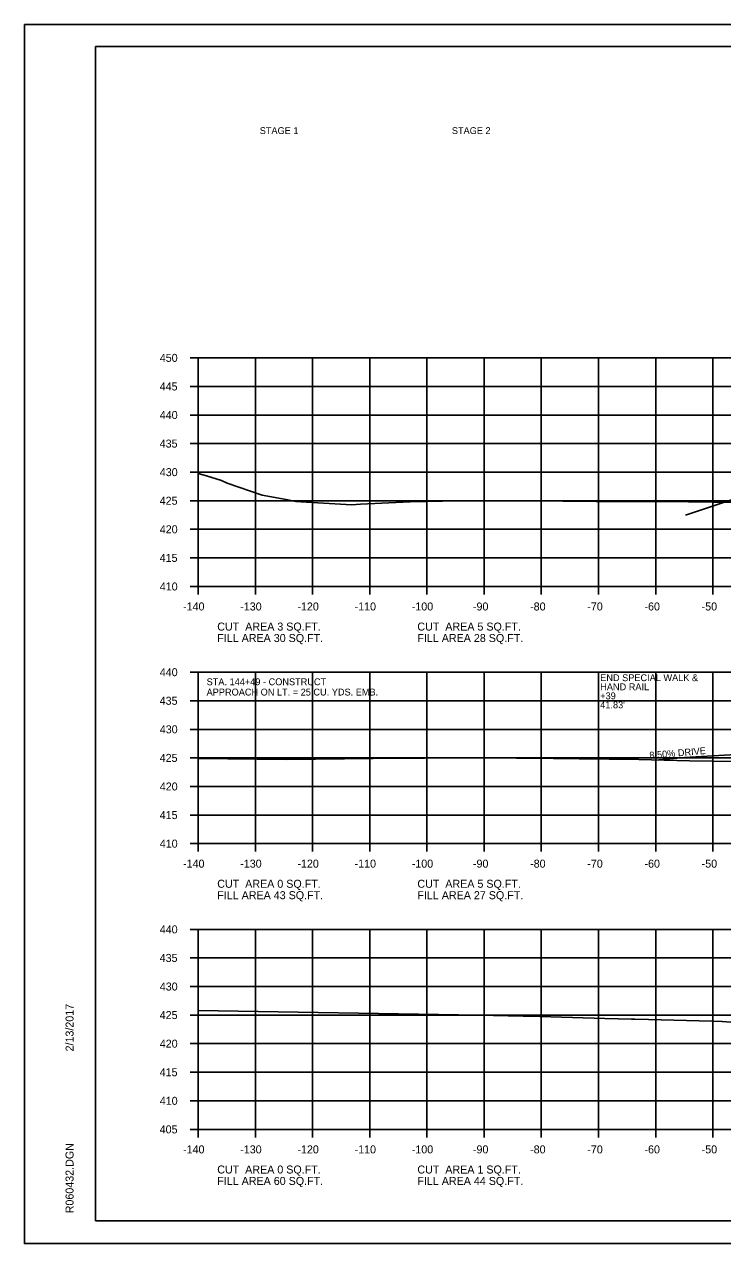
# Model space of a CAD drawing. Extents: x 1538688 to 1540766, y 656250 to 671912.
# Drawn here: x 1538687.8 to 1538809.9, y 663164.7 to 663378.1 of the extents above; entities that cross this region are included whole.
import ezdxf

# ---------------------------------------------------------------- set-up
doc = ezdxf.new("R2010")
doc.units = 0
for name, color, linetype in [('16', 7, 'Continuous'), ('18', 7, 'Continuous'), ('22', 7, 'Continuous'), ('26', 7, 'Continuous'), ('7', 7, 'Continuous'), ('Borings', 7, 'Continuous'), ('Default', 7, 'Continuous'), ('Horizontal Alignment', 7, 'Continuous'), ('RipRap', 7, 'Continuous')]:
    doc.layers.add(name, color=color, linetype=linetype)

msp = doc.modelspace()

# ---------------------------------------------------------------- linework, layer by layer
at = {"layer": '16'}
for p, q in [((1538798.14, 663249.33), (1538803.21, 663249.76)), ((1538803.21, 663249.76), (1538813.2, 663250.36))]:
    msp.add_line(p, q, dxfattribs=at)
at = {"layer": '18'}
for points in [[(1538718.18, 663299.49), (1538719.63, 663299.03), (1538722.26, 663298.22), (1538723.24, 663297.8), (1538729.37, 663295.65), (1538733.58, 663294.89), (1538735.27, 663294.58), (1538736.12, 663294.5), (1538745.06, 663294), (1538746.56, 663294.1), (1538755.22, 663294.53), (1538760.88, 663294.62), (1538767.87, 663294.66), (1538770.41, 663294.68), (1538781.93, 663294.6), (1538787.76, 663294.56), (1538799.62, 663294.54), (1538816.79, 663294.35)], [(1538718.18, 663249.57), (1538733.69, 663249.4), (1538753.85, 663249.63), (1538757.76, 663249.64), (1538761.4, 663249.69), (1538761.85, 663249.72), (1538763.1, 663249.71), (1538767.33, 663249.69), (1538780.28, 663249.62), (1538784.81, 663249.53), (1538795.23, 663249.4), (1538804.12, 663249.2), (1538816.39, 663249.02)], [(1538718.18, 663205.48), (1538767.19, 663204.69), (1538775.02, 663204.52), (1538775.4, 663204.52), (1538776.03, 663204.49), (1538789.31, 663204.11), (1538793.98, 663203.98), (1538794.55, 663203.96), (1538796.93, 663203.9), (1538808.02, 663203.62), (1538809.78, 663203.55), (1538818.94, 663202.89)]]:
    msp.add_lwpolyline(points, dxfattribs=at)
at = {"layer": '22'}
for p, q in [((1538718.18, 663319.7), (1538998.18, 663319.7)), ((1538718.18, 663279.7), (1538718.18, 663319.7)), ((1538728.18, 663279.7), (1538728.18, 663319.7)), ((1538738.18, 663279.7), (1538738.18, 663319.7)), ((1538748.18, 663279.7), (1538748.18, 663319.7)), ((1538758.18, 663279.7), (1538758.18, 663319.7)), ((1538768.18, 663279.7), (1538768.18, 663319.7)), ((1538778.18, 663279.7), (1538778.18, 663319.7)), ((1538788.18, 663279.7), (1538788.18, 663319.7)), ((1538798.18, 663279.7), (1538798.18, 663319.7)), ((1538808.18, 663279.7), (1538808.18, 663319.7)), ((1538718.18, 663314.7), (1538998.18, 663314.7)), ((1538718.18, 663309.7), (1538998.18, 663309.7)), ((1538718.18, 663304.7), (1538998.18, 663304.7)), ((1538718.18, 663299.7), (1538998.18, 663299.7)), ((1538718.18, 663294.7), (1538998.18, 663294.7)), ((1538718.18, 663289.7), (1538998.18, 663289.7)), ((1538718.18, 663284.7), (1538998.18, 663284.7)), ((1538718.18, 663279.7), (1538998.18, 663279.7)), ((1538718.18, 663264.7), (1538998.18, 663264.7)), ((1538718.18, 663234.7), (1538718.18, 663264.7)), ((1538728.18, 663234.7), (1538728.18, 663264.7)), ((1538738.18, 663234.7), (1538738.18, 663264.7)), ((1538748.18, 663234.7), (1538748.18, 663264.7)), ((1538758.18, 663234.7), (1538758.18, 663264.7)), ((1538768.18, 663234.7), (1538768.18, 663264.7)), ((1538778.18, 663234.7), (1538778.18, 663264.7)), ((1538788.18, 663234.7), (1538788.18, 663264.7)), ((1538798.18, 663234.7), (1538798.18, 663264.7)), ((1538808.18, 663234.7), (1538808.18, 663264.7)), ((1538718.18, 663259.7), (1538998.18, 663259.7)), ((1538718.18, 663254.7), (1538998.18, 663254.7)), ((1538718.18, 663249.7), (1538998.18, 663249.7)), ((1538718.18, 663244.7), (1538998.18, 663244.7)), ((1538718.18, 663239.7), (1538998.18, 663239.7)), ((1538718.18, 663234.7), (1538998.18, 663234.7)), ((1538718.18, 663219.7), (1538998.18, 663219.7)), ((1538718.18, 663184.7), (1538718.18, 663219.7)), ((1538728.18, 663184.7), (1538728.18, 663219.7)), ((1538738.18, 663184.7), (1538738.18, 663219.7)), ((1538748.18, 663184.7), (1538748.18, 663219.7)), ((1538758.18, 663184.7), (1538758.18, 663219.7)), ((1538768.18, 663184.7), (1538768.18, 663219.7)), ((1538778.18, 663184.7), (1538778.18, 663219.7)), ((1538788.18, 663184.7), (1538788.18, 663219.7)), ((1538798.18, 663184.7), (1538798.18, 663219.7)), ((1538808.18, 663184.7), (1538808.18, 663219.7)), ((1538718.18, 663214.7), (1538998.18, 663214.7)), ((1538718.18, 663209.7), (1538998.18, 663209.7)), ((1538718.18, 663204.7), (1538998.18, 663204.7)), ((1538718.18, 663199.7), (1538998.18, 663199.7)), ((1538718.18, 663194.7), (1538998.18, 663194.7)), ((1538718.18, 663189.7), (1538998.18, 663189.7)), ((1538718.18, 663184.7), (1538998.18, 663184.7))]:
    msp.add_line(p, q, dxfattribs=at)
at = {"layer": '26'}
for p, q in [((1538687.78, 663378.05), (1539021.11, 663378.05)), ((1538687.78, 663164.72), (1539021.11, 663164.72))]:
    msp.add_line(p, q, dxfattribs=at)
msp.add_lwpolyline([(1538687.77, 663378.05), (1539021.11, 663378.05), (1539021.11, 663164.71), (1538687.77, 663164.71)], close=True, dxfattribs=at)
msp.add_lwpolyline([(1538816.67, 663296.6), (1538811.99, 663295.04), (1538803.4, 663292.18)], dxfattribs=at)
at = {"layer": 'Borings'}
for p, q in [((1538716.78, 663319.7), (1538718.18, 663319.7)), ((1538718.18, 663279.7), (1538718.18, 663319.7)), ((1538716.78, 663314.7), (1538718.18, 663314.7)), ((1538716.78, 663309.7), (1538718.18, 663309.7)), ((1538716.78, 663304.7), (1538718.18, 663304.7)), ((1538716.78, 663299.7), (1538718.18, 663299.7)), ((1538716.78, 663294.7), (1538718.18, 663294.7)), ((1538716.78, 663289.7), (1538718.18, 663289.7)), ((1538716.78, 663284.7), (1538718.18, 663284.7)), ((1538716.78, 663279.7), (1538718.18, 663279.7)), ((1538718.18, 663279.7), (1538998.18, 663279.7)), ((1538718.18, 663278.3), (1538718.18, 663279.7)), ((1538728.18, 663278.3), (1538728.18, 663279.7)), ((1538738.18, 663278.3), (1538738.18, 663279.7)), ((1538748.18, 663278.3), (1538748.18, 663279.7)), ((1538758.18, 663278.3), (1538758.18, 663279.7)), ((1538768.18, 663278.3), (1538768.18, 663279.7)), ((1538778.18, 663278.3), (1538778.18, 663279.7)), ((1538788.18, 663278.3), (1538788.18, 663279.7)), ((1538798.18, 663278.3), (1538798.18, 663279.7)), ((1538808.18, 663278.3), (1538808.18, 663279.7)), ((1538716.78, 663264.7), (1538718.18, 663264.7)), ((1538718.18, 663234.7), (1538718.18, 663264.7)), ((1538716.78, 663259.7), (1538718.18, 663259.7)), ((1538716.78, 663254.7), (1538718.18, 663254.7)), ((1538716.78, 663249.7), (1538718.18, 663249.7)), ((1538716.78, 663244.7), (1538718.18, 663244.7)), ((1538716.78, 663239.7), (1538718.18, 663239.7)), ((1538716.78, 663234.7), (1538718.18, 663234.7)), ((1538718.18, 663234.7), (1538998.18, 663234.7)), ((1538718.18, 663233.3), (1538718.18, 663234.7)), ((1538728.18, 663233.3), (1538728.18, 663234.7)), ((1538738.18, 663233.3), (1538738.18, 663234.7)), ((1538748.18, 663233.3), (1538748.18, 663234.7)), ((1538758.18, 663233.3), (1538758.18, 663234.7)), ((1538768.18, 663233.3), (1538768.18, 663234.7)), ((1538778.18, 663233.3), (1538778.18, 663234.7)), ((1538788.18, 663233.3), (1538788.18, 663234.7)), ((1538798.18, 663233.3), (1538798.18, 663234.7)), ((1538808.18, 663233.3), (1538808.18, 663234.7)), ((1538716.78, 663219.7), (1538718.18, 663219.7)), ((1538718.18, 663184.7), (1538718.18, 663219.7)), ((1538716.78, 663214.7), (1538718.18, 663214.7)), ((1538716.78, 663209.7), (1538718.18, 663209.7)), ((1538716.78, 663204.7), (1538718.18, 663204.7)), ((1538716.78, 663199.7), (1538718.18, 663199.7)), ((1538716.78, 663194.7), (1538718.18, 663194.7)), ((1538716.78, 663189.7), (1538718.18, 663189.7)), ((1538716.78, 663184.7), (1538718.18, 663184.7)), ((1538718.18, 663184.7), (1538998.18, 663184.7)), ((1538718.18, 663183.3), (1538718.18, 663184.7)), ((1538728.18, 663183.3), (1538728.18, 663184.7)), ((1538738.18, 663183.3), (1538738.18, 663184.7)), ((1538748.18, 663183.3), (1538748.18, 663184.7)), ((1538758.18, 663183.3), (1538758.18, 663184.7)), ((1538768.18, 663183.3), (1538768.18, 663184.7)), ((1538778.18, 663183.3), (1538778.18, 663184.7)), ((1538788.18, 663183.3), (1538788.18, 663184.7)), ((1538798.18, 663183.3), (1538798.18, 663184.7)), ((1538808.18, 663183.3), (1538808.18, 663184.7))]:
    msp.add_line(p, q, dxfattribs=at)
at = {"layer": 'RipRap'}
for p, q in [((1538700.18, 663374.16), (1539016.36, 663374.16)), ((1538700.18, 663168.7), (1538700.18, 663374.16)), ((1538700.18, 663168.7), (1538700.18, 663168.7)), ((1539016.36, 663168.7), (1538700.18, 663168.7))]:
    msp.add_line(p, q, dxfattribs=at)

# ---------------------------------------------------------------- texts
at = {"layer": '16'}
msp.add_text('8.50% DRIVE', height=1.2, rotation=4.8585, dxfattribs=at).set_placement((1538797.13, 663249.55))
at = {"layer": '7'}
for s, p in [('STA. 144+49 - CONSTRUCT', (1538719.64, 663262.42)), ('END SPECIAL WALK &', (1538788.48, 663263.13)), ('HAND RAIL', (1538788.48, 663261.54)), ('APPROACH ON LT. = 25 CU. YDS. EMB.', (1538719.64, 663260.62)), ('+39', (1538788.48, 663259.96)), ("41.83'", (1538788.48, 663258.38))]:
    msp.add_text(s, height=1.2, dxfattribs=at).set_placement(p)
at = {"layer": 'Default'}
for s, p in [('STAGE 1', (1538728.93, 663358.86)), ('STAGE 2', (1538762.53, 663358.86))]:
    msp.add_text(s, height=1.2, dxfattribs=at).set_placement(p)
at = {"layer": 'Horizontal Alignment'}
for s, p in [('450', (1538711.45, 663319)), ('445', (1538711.43, 663314)), ('440', (1538711.45, 663309)), ('435', (1538711.43, 663304)), ('430', (1538711.45, 663299)), ('425', (1538711.43, 663294)), ('420', (1538711.45, 663289)), ('415', (1538711.43, 663284)), ('410', (1538711.45, 663279)), ('-140', (1538715.52, 663275.5)), ('-130', (1538725.52, 663275.5)), ('-120', (1538735.52, 663275.5)), ('-110', (1538745.52, 663275.5)), ('-100', (1538755.52, 663275.5)), ('-90', (1538766.22, 663275.5)), ('-80', (1538776.22, 663275.5)), ('-70', (1538786.22, 663275.5)), ('-60', (1538796.22, 663275.5)), ('-50', (1538806.22, 663275.5)), ('CUT  AREA 3 SQ.FT.', (1538721.5, 663271.98)), ('CUT  AREA 5 SQ.FT.', (1538756.5, 663271.98)), ('FILL AREA 30 SQ.FT.', (1538721.5, 663269.98)), ('FILL AREA 28 SQ.FT.', (1538756.5, 663269.98)), ('440', (1538711.45, 663264)), ('435', (1538711.43, 663259)), ('430', (1538711.45, 663254)), ('425', (1538711.43, 663249)), ('420', (1538711.45, 663244)), ('415', (1538711.43, 663239)), ('410', (1538711.45, 663234)), ('-140', (1538715.52, 663230.5)), ('-130', (1538725.52, 663230.5)), ('-120', (1538735.52, 663230.5)), ('-110', (1538745.52, 663230.5)), ('-100', (1538755.52, 663230.5)), ('-90', (1538766.22, 663230.5)), ('-80', (1538776.22, 663230.5)), ('-70', (1538786.22, 663230.5)), ('-60', (1538796.22, 663230.5)), ('-50', (1538806.22, 663230.5)), ('CUT  AREA 0 SQ.FT.', (1538721.5, 663226.98)), ('CUT  AREA 5 SQ.FT.', (1538756.5, 663226.98)), ('FILL AREA 43 SQ.FT.', (1538721.5, 663224.98)), ('FILL AREA 27 SQ.FT.', (1538756.5, 663224.98)), ('440', (1538711.45, 663219)), ('435', (1538711.43, 663214)), ('430', (1538711.45, 663209)), ('425', (1538711.43, 663204)), ('420', (1538711.45, 663199)), ('415', (1538711.43, 663194)), ('410', (1538711.45, 663189)), ('405', (1538711.43, 663184)), ('-140', (1538715.52, 663180.5)), ('-130', (1538725.52, 663180.5)), ('-120', (1538735.52, 663180.5)), ('-110', (1538745.52, 663180.5)), ('-100', (1538755.52, 663180.5)), ('-90', (1538766.22, 663180.5)), ('-80', (1538776.22, 663180.5)), ('-70', (1538786.22, 663180.5)), ('-60', (1538796.22, 663180.5)), ('-50', (1538806.22, 663180.5)), ('CUT  AREA 0 SQ.FT.', (1538721.5, 663176.98)), ('CUT  AREA 1 SQ.FT.', (1538756.5, 663176.98)), ('FILL AREA 60 SQ.FT.', (1538721.5, 663174.98)), ('FILL AREA 44 SQ.FT.', (1538756.5, 663174.98))]:
    msp.add_text(s, height=1.4, dxfattribs=at).set_placement(p)
at = {"layer": 'RipRap'}
for s, p in [('2/13/2017', (1538696.37, 663198.34)), ('R060432.DGN', (1538696.37, 663170.02))]:
    msp.add_text(s, height=1.4, rotation=90, dxfattribs=at).set_placement(p)

doc.saveas('drawing.dxf')
